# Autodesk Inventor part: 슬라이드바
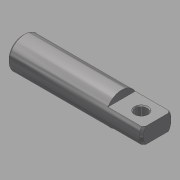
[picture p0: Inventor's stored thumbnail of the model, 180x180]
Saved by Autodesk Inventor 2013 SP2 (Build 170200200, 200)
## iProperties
Created: 2015-12
Part Number: 슬라이드바
Material: 스테인리스강
Document SubType Name: Modeling
Designer: mduedu
Density: 8.08 g/cm^3
Author: mduedu
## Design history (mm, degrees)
sketch "스케치1"
  geometry: L1 (-34, 0)-(34, 0); L2 (-34, 0)-(-34, 8); L3 (-34, 8)-(34, 8); L4 (34, 8)-(34, 0); 2 further points
  constraints: 8 end point, 2 perpendicular, 1 coincident, 1 horizontal, 1 midpoint, 1 vertical
  dimensions: "d0" = 68 distance of L2.end L3.end; "d2" = 16 diameter of L3 L1
revolve "회전1" sketch "스케치1" stored, may be unused: angle "d3" = 90 deg
sketch "스케치2"
  geometry: L1 (34, -8)-(34, 8) reference; L2 (0, 0)-(34, 0); L3 (34, 4)-(16, 4); L4 (16, 4)-(16, 8); L5 (16, 8)-(34, 8); L6 (34, 8)-(34, 4); L7 (-34, 8)-(34, 8) reference
  constraints: 10 end point, 2 parallel, 1 collinear, 1 horizontal, 1 midpoint, 1 perpendicular, 1 point on line
  dimensions: "d4" = 18 distance of L4.end L5.end; "d6" = 4 distance between parallel lines of L3 L2
extrude "돌출1" cut sketch "스케치2" stored distance "d8" = 10; taper "d9" = 0 deg
sketch "스케치3"
  geometry: L1 (0, 0)-(0, -13.856) reference; 2 further points
  constraints: 1 horizontal alignment
  dimensions: "d10" = 10 distance from line of point (10, -6.928) L1
hole "구멍1" sketch "스케치3" at (10, -6.928) diameter "d11" = 6; stored, may be unused: countersink angle "d15" = 90 deg, drill point angle "d17" = 118 deg; dims "d12" = 6, "d13" = 4, "d14" = 2, "d16" = 8
chamfer "모따기1" distance "d18" = 0.5; stored, may be unused: second distance "d19" = 2, angle "d20" = 45 deg
chamfer "모따기2" distance "d21" = 1; stored, may be unused: second distance "d22" = 2, angle "d23" = 45 deg
hole "구멍2" diameter "d26" = 4.917; stored, may be unused: countersink angle "d30" = 90 deg, drill point angle "d32" = 118 deg; dims "d24" = 10, "d25" = 10, "d27" = 12, "d28" = 4, "d29" = 2, "d31" = 13
chamfer "모따기3" distance "d33" = 1; stored, may be unused: second distance "d34" = 2, angle "d35" = 45 deg
node "솔리드1"
mirror "대칭1"
